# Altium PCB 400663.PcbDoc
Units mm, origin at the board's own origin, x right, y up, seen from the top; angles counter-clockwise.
Board outline 63.5 x 80 mm, 6 copper layers (Top Layer, Mid-Layer 1, Mid-Layer 2, Mid-Layer 3, Mid-Layer 4, Bottom Layer), stack 1.671 mm thick; 78 components, 32 nets, 270 pads, 197 vias.
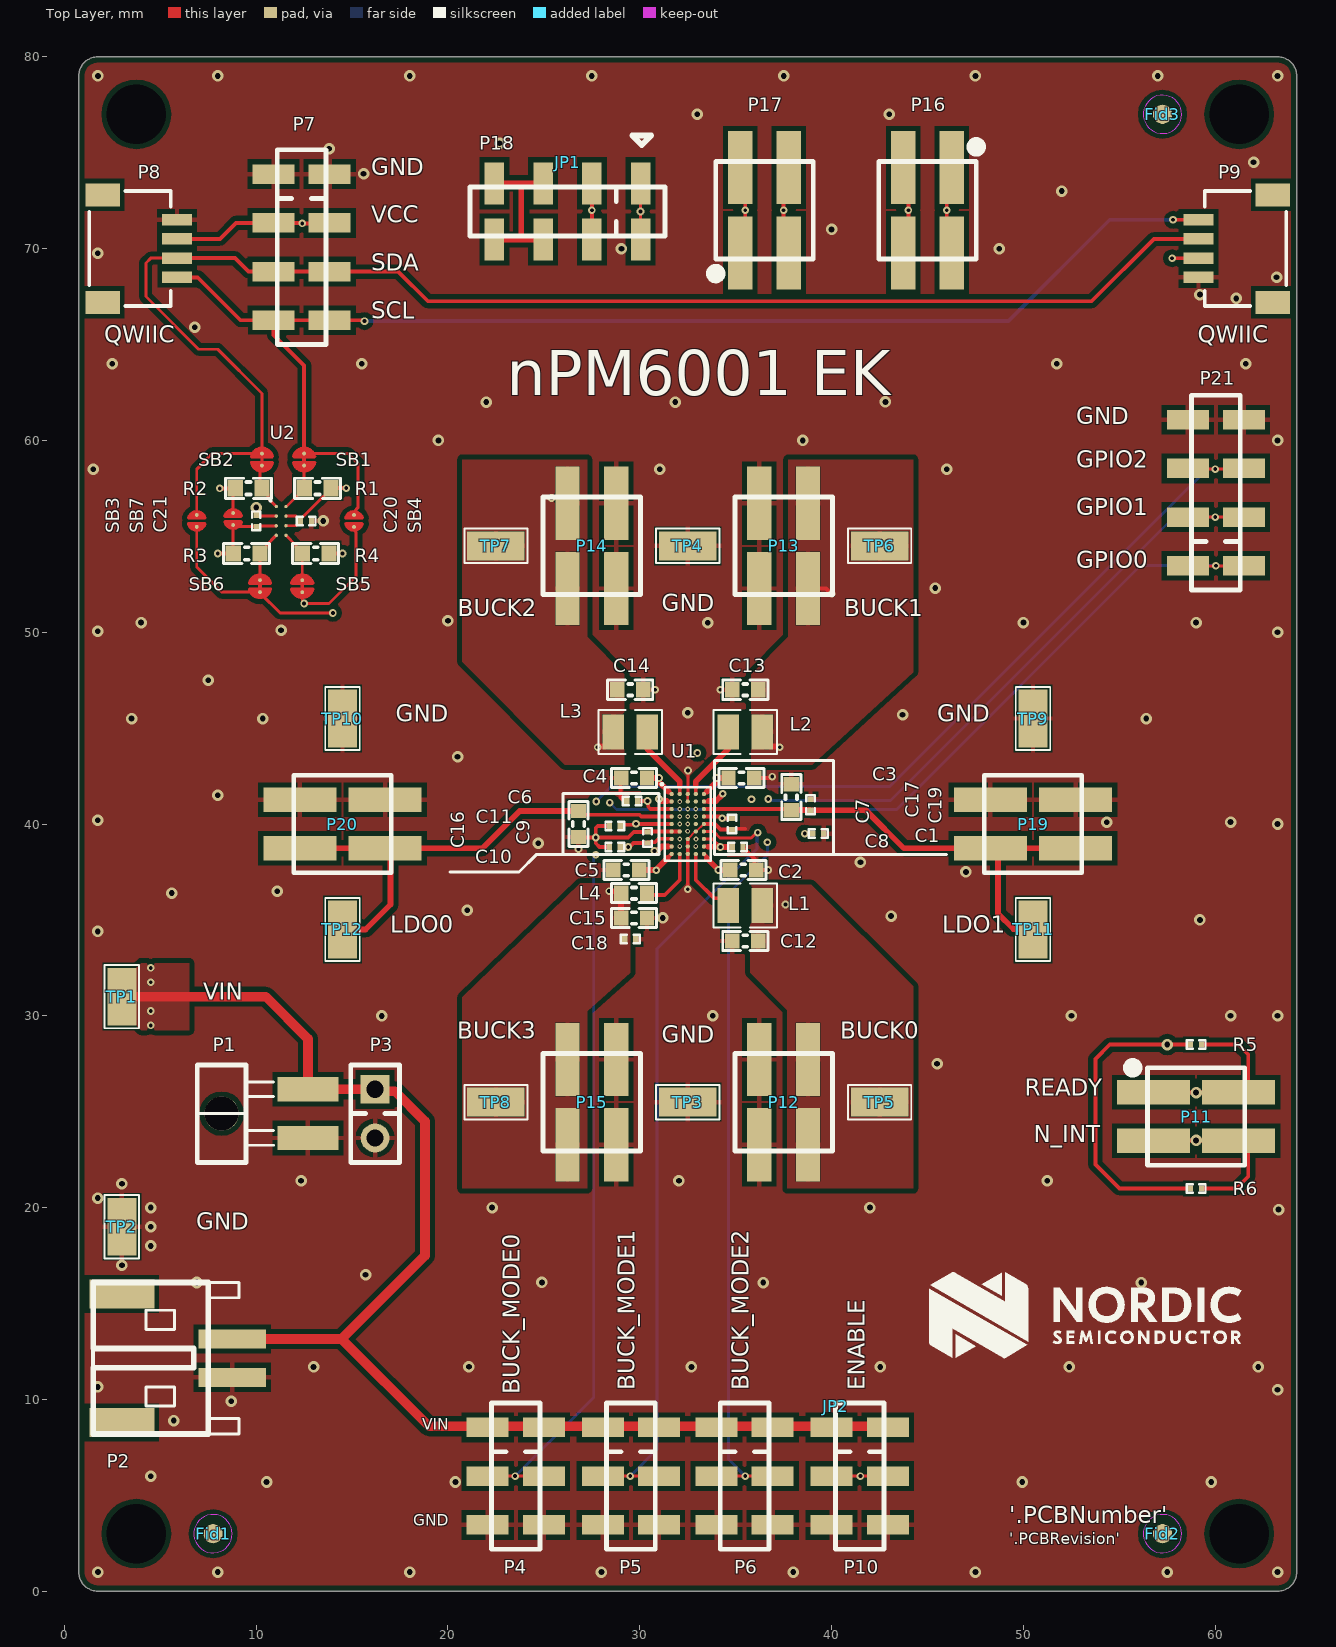
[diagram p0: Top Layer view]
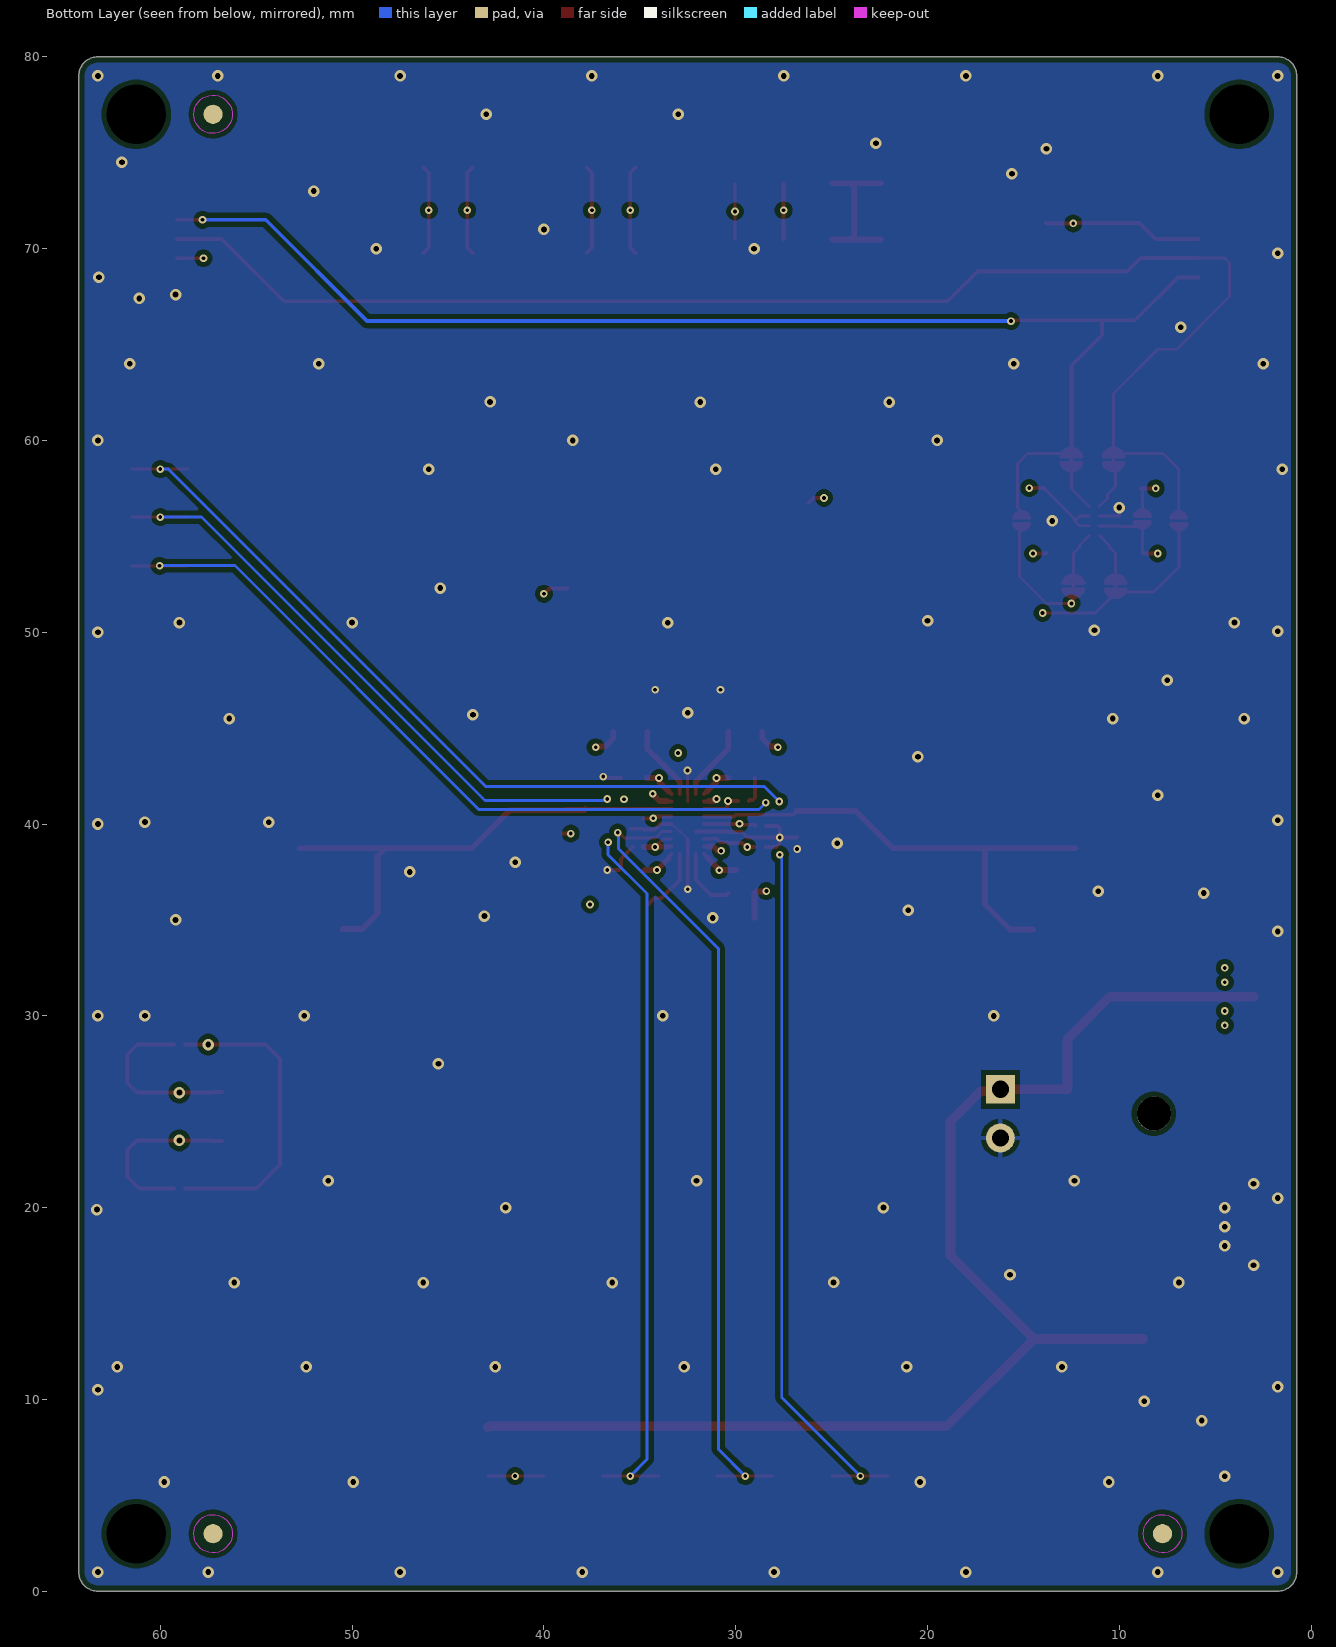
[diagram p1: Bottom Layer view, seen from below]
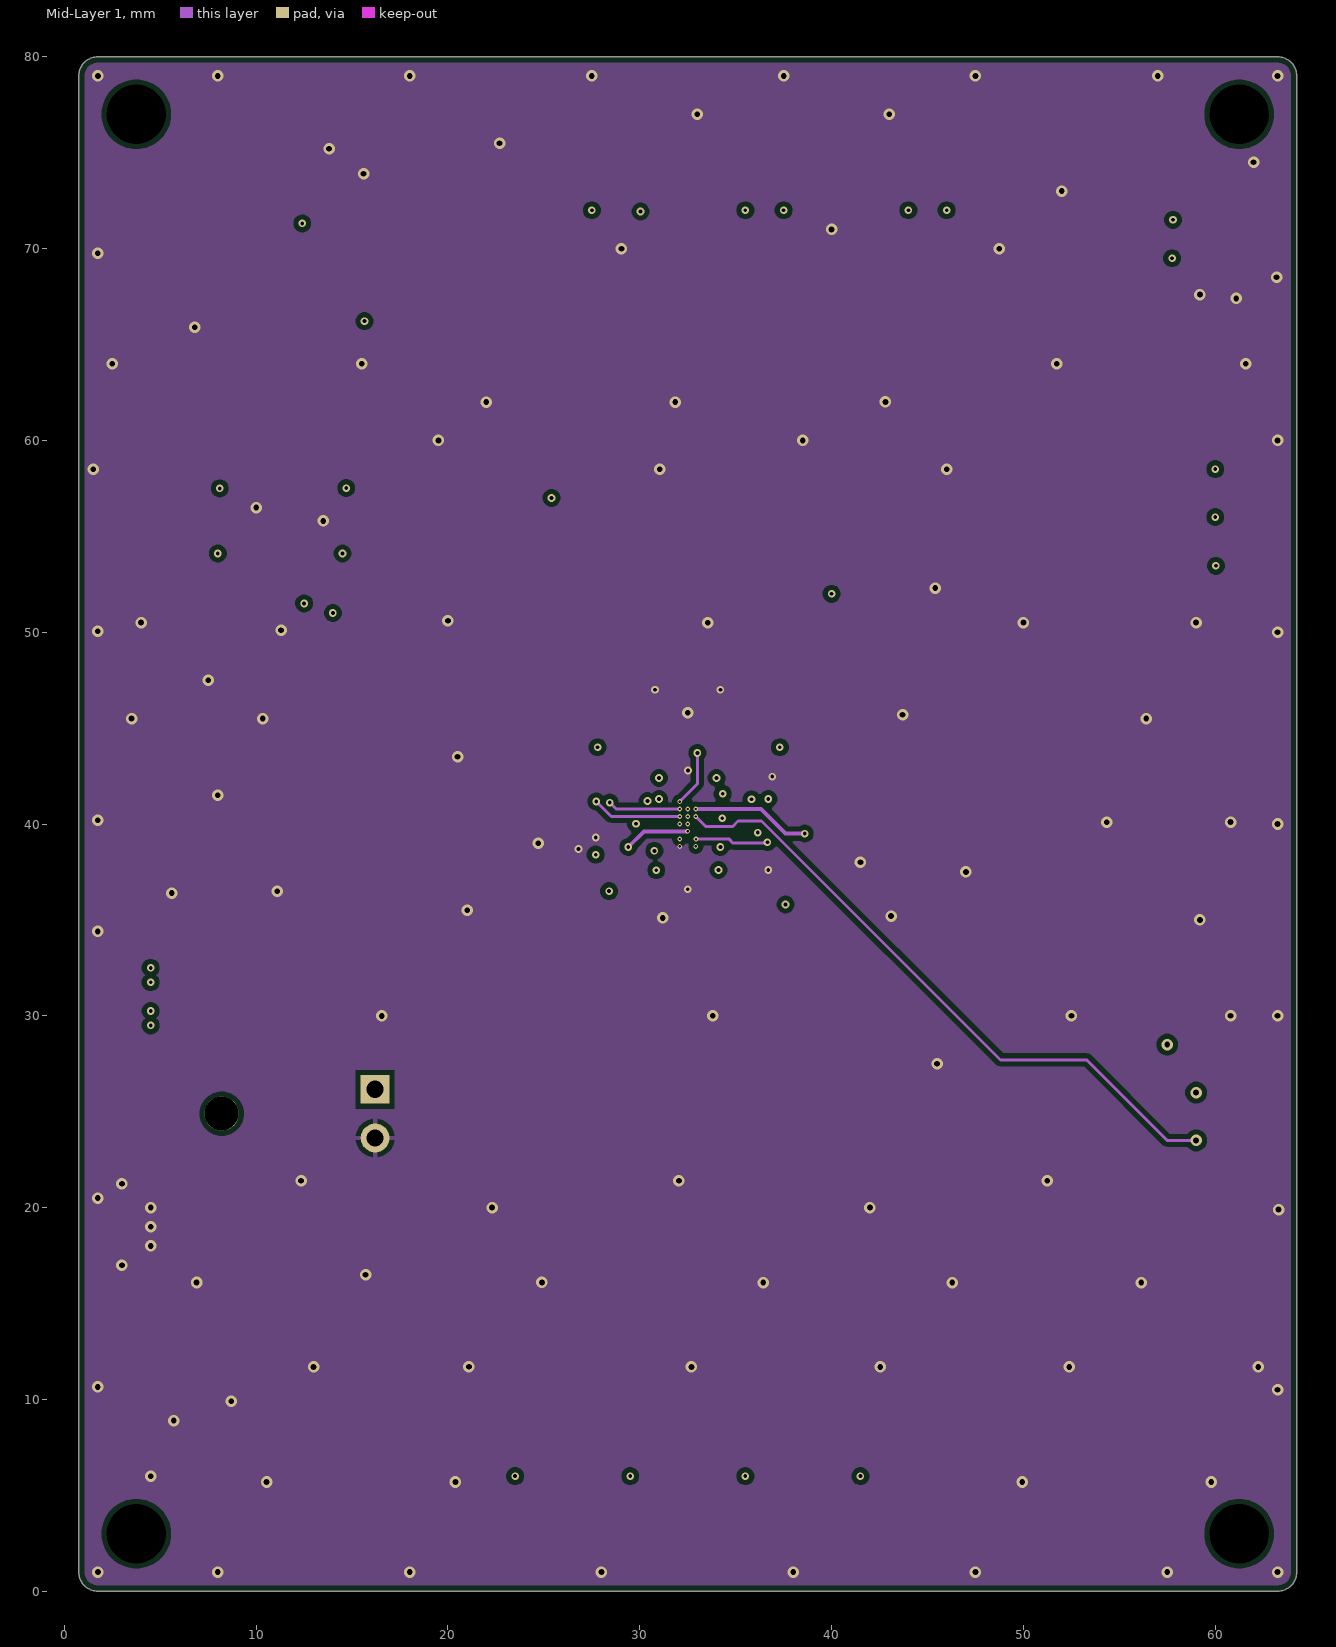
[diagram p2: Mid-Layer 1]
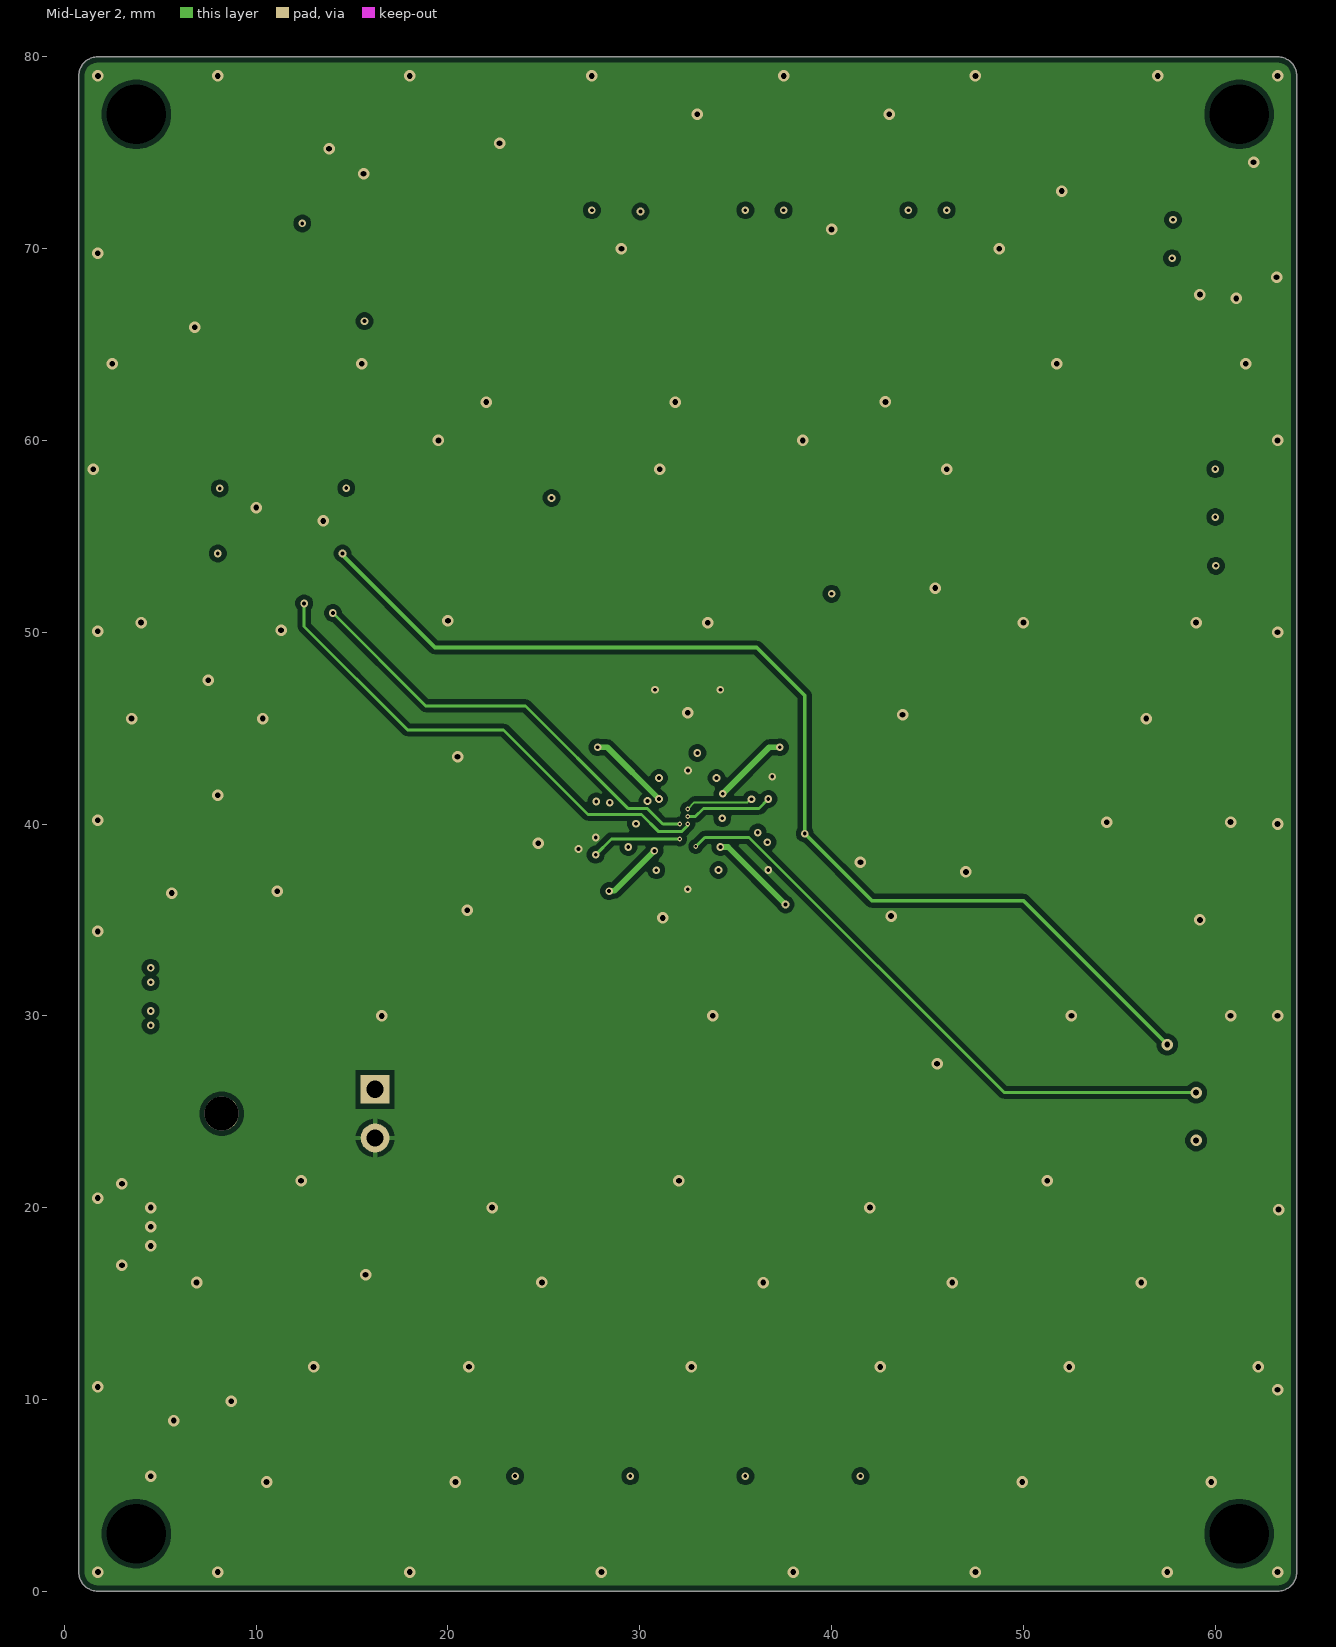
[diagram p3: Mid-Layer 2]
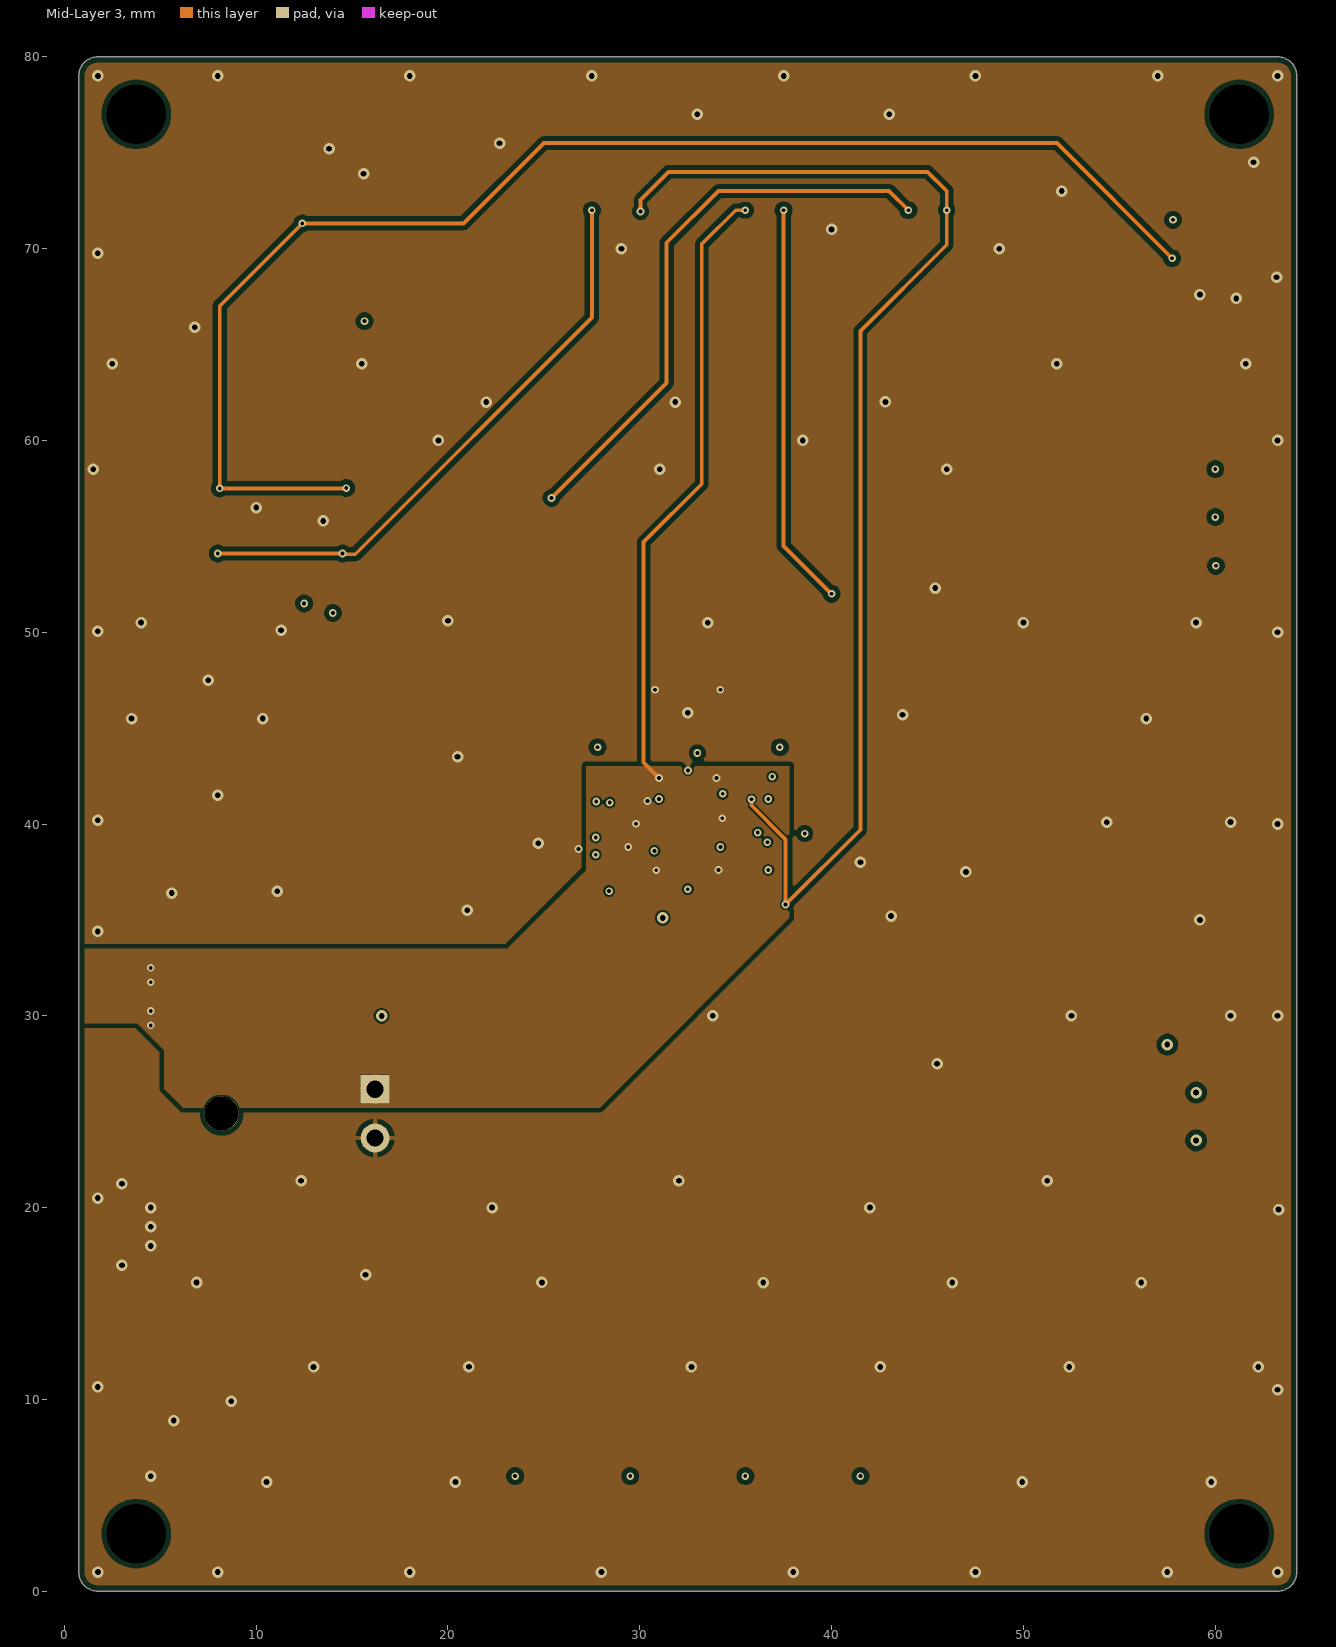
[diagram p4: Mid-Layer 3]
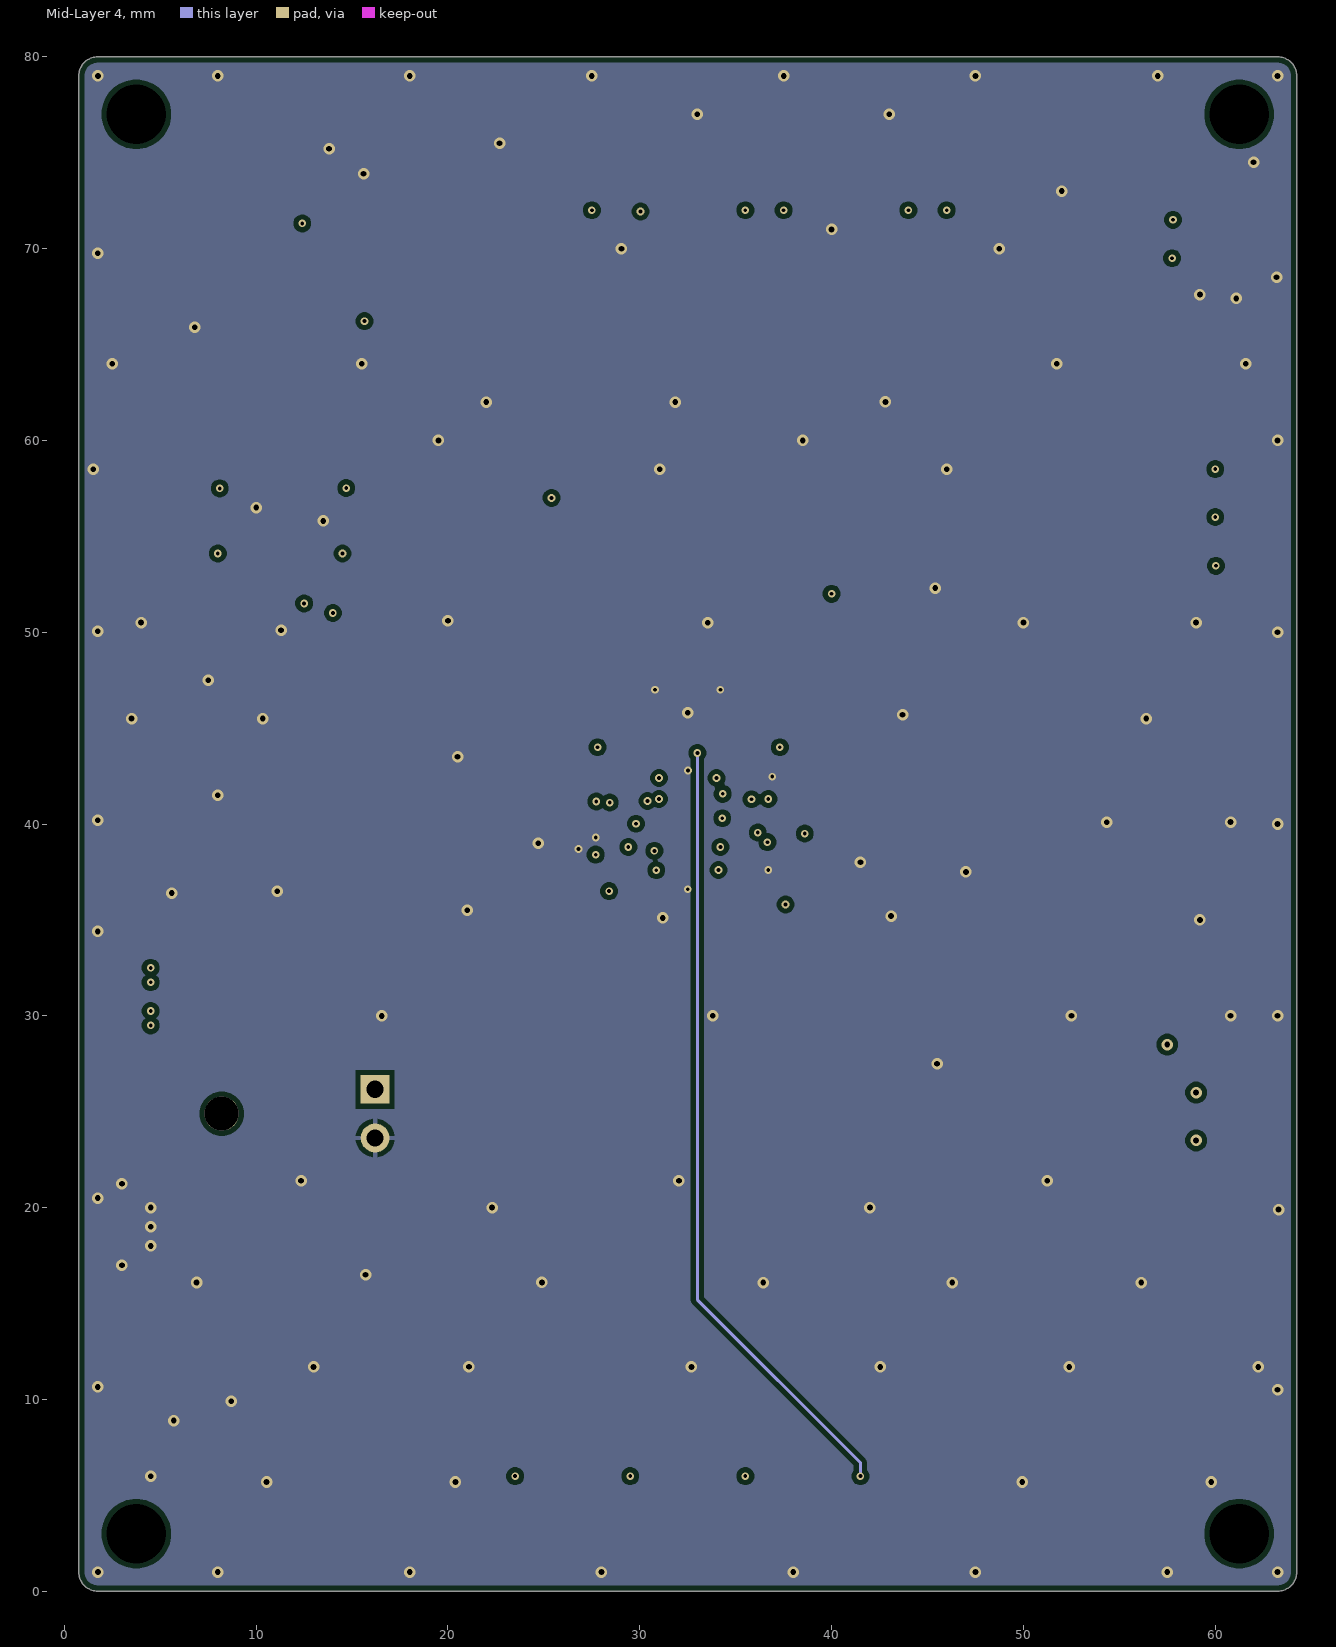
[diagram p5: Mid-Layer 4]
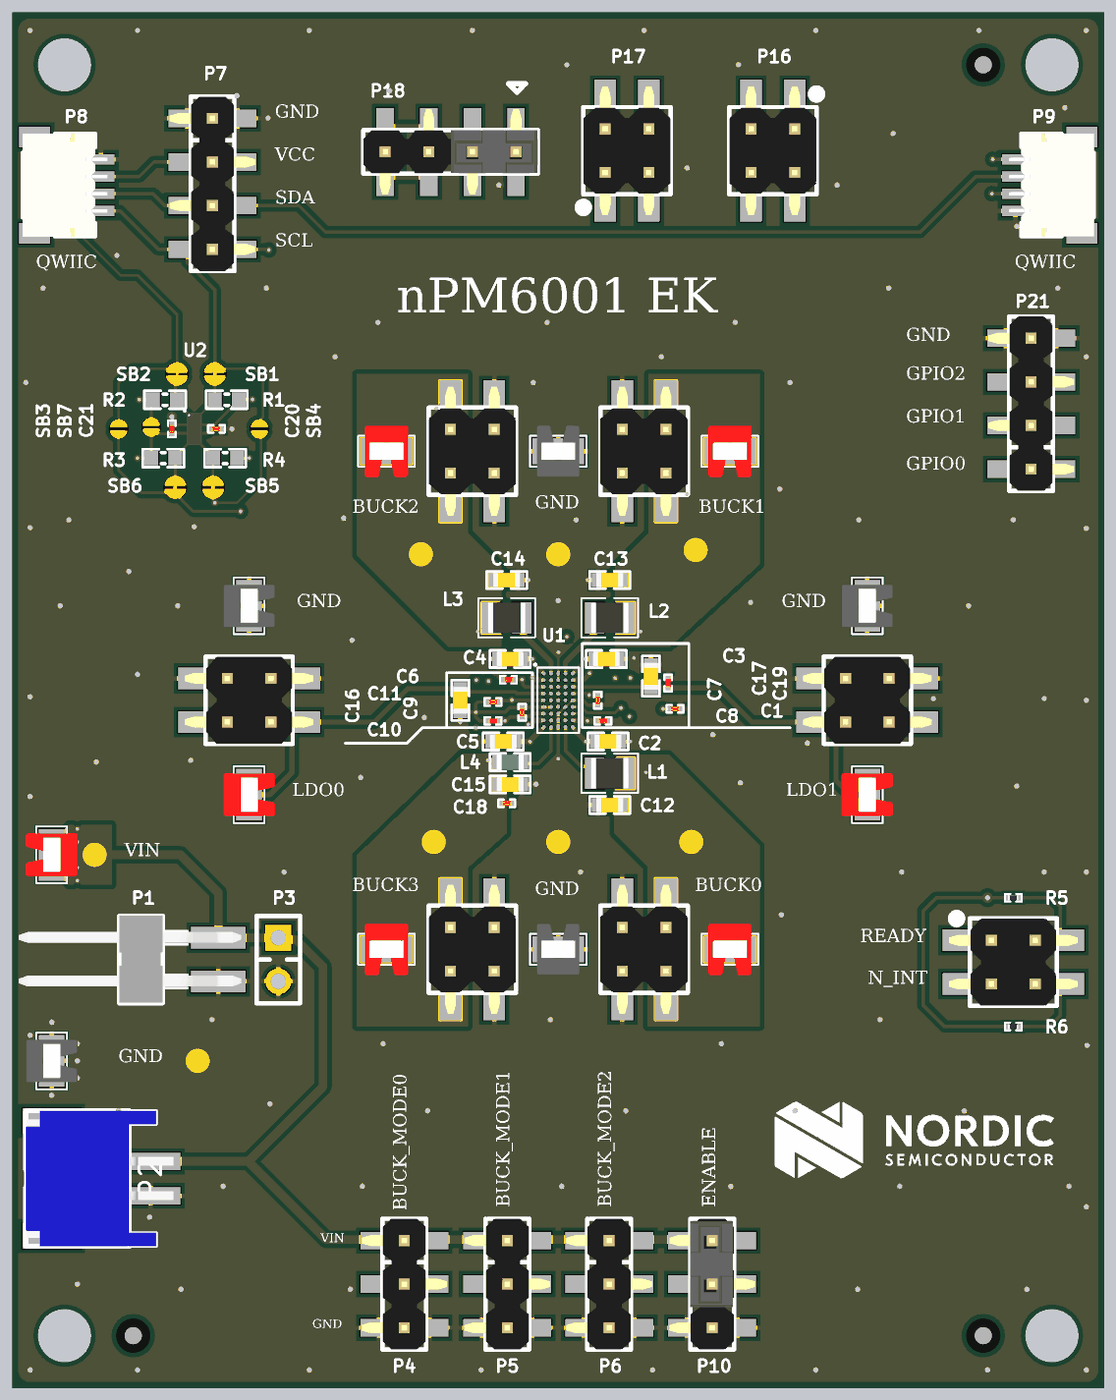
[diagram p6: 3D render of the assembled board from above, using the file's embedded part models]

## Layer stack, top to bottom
Top Solder: solder mask 0.0102, Solder Resist, Dk 3.5
Top Layer: signal copper 0.018
Dielectric1: prepreg 0.065, FR-4, Dk 4.2
Mid-Layer 1: signal copper 0.035
Dielectric2: core 0.51, FR-4, Dk 4.2
Mid-Layer 2: signal copper 0.035
Dielectric3: prepreg 0.345, FR-4, Dk 4.2
Mid-Layer 3: signal copper 0.035
Dielectric 5: core 0.51, FR-4, Dk 4.2
Mid-Layer 4: signal copper 0.035
Dielectric 4: prepreg 0.065, FR-4, Dk 4.2
Bottom Layer: signal copper 0.018
Bottom Solder: solder mask 0.0102, Solder Resist, Dk 3.5

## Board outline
0.75,1 ccw(c1.75,1) 1.75,0 63.25,0 ccw(c63.25,1) 64.25,1 64.25,79 ccw(c63.25,79) 63.25,80 1.75,80 ccw(c1.75,79) 0.75,79

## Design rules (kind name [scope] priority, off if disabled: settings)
BoardOutlineClearance [All] p1: gap=0.3 ignorepadtopadclearanceinfootprint=FALSE
Clearance Clearance_MicroVia [AsMM(ViaDiameter) = 0.30 vs AsMM(ViaDiameter) = 0.3] p1: gap=0.1 ignorepadtopadclearanceinfootprint=FALSE except(0: Arc-Hole Track-Hole SMDPad-Hole THPad-Hole Via-Hole Fill-Hole Poly-Hole Region-Hole Text-Hole)
Clearance Polygon_Clearance [(InNamedPolygon('Top_Layer-GND')) or (InNamedPolygon('Bottom_Layer-GND')) or (InNamedPolygon('Mid_Layer_1-GND')) or (InNamedPolygon('Mid_Layer_2-GND')) or (InNamedPolygon('Mid_Layer_3-GND')) or (InNamedPolygon('Mid_Layer_4-GND'))] p2: gap=0.254 ignorepadtopadclearanceinfootprint=FALSE except(0: Arc-Hole Track-Hole SMDPad-Hole THPad-Hole Via-Hole Fill-Hole Poly-Hole Region-Hole Text-Hole)
Clearance [All] p3: gap=0.1 ignorepadtopadclearanceinfootprint=FALSE
ComponentClearance [All] p1: gap=0.05 collisioncheckmode=3 verticalgap=0 showdistances=FALSE
DiffPairsRouting [All] p1: maxlimit=0.254 minlimit=0.15 mostfreqgap=0.254 toplayer_maxgap=0.15 toplayer_prefgap=0.15 toplayer_minwidth=0.381 toplayer_maxwidth=0.381 toplayer_prefwidth=0.381 midlayer1_mingap=0.254 midlayer1_minwidth=0.381 midlayer1_maxwidth=0.381 midlayer1_prefwidth=0.381 midlayer2_mingap=0.254 midlayer2_minwidth=0.381 midlayer2_maxwidth=0.381 midlayer2_prefwidth=0.381 midlayer3_mingap=0.254 midlayer3_minwidth=0.381 midlayer3_maxwidth=0.381 midlayer3_prefwidth=0.381 midlayer4_mingap=0.254 midlayer4_minwidth=0.381 midlayer4_maxwidth=0.381 midlayer4_prefwidth=0.381 bottomlayer_maxgap=0.15 bottomlayer_prefgap=0.15 bottomlayer_minwidth=0.381 bottomlayer_maxwidth=0.381 bottomlayer_prefwidth=0.381 maxuncoupledlength=12.7
FabricationTestPointUsage TestPointUsage [All] p1: valid=0 allowmultiple=FALSE
FabricationTestpoint Testpoint [All] p1: side=3 testpointundercomponent=TRUE minsize=1.016 maxsize=2.54 preferedsize=1.524 minholesize=0 maxholesize=1.016 preferedholesize=0.813 testpointgrid=0.025 allowsidetop=TRUE allowsidebottom=TRUE usegrid=TRUE gridtolerance=0
HoleSize [All] p1: absolutevalues=TRUE maxlimit=5 minlimit=0.1 maxpercent=80.000 minpercent=20.000
MinimumAnnularRing [All] p1 off: minimumring=0.152
PolygonConnect "Power lines connection" [InNetClass('POWER') vs InNetClass('POWER')] p1: connectstyle=Direct reliefconductorwidth=0.254 reliefentries=4 polygonreliefangle="90 Angle" airgapwidth=0.254
PolygonConnect PolygonConnect_1 [isVia and innet(gnd)] p2: connectstyle=Direct reliefconductorwidth=0.254 reliefentries=4 polygonreliefangle="90 Angle" airgapwidth=0.254
PolygonConnect [Not InNetClass('POWER') vs Not InNetClass('POWER')] p3: connectstyle=Relief reliefconductorwidth=0.254 reliefentries=4 polygonreliefangle="90 Angle" airgapwidth=0.254
RoutingVias [All] p1: holewidth=0.711 width=1.27 viastyle="Through Hole" minholewidth=0.711 minwidth=1.27 maxholewidth=0.711 maxwidth=1.27 useviatemplates=TRUE viatemplateguid#1={E10108A7-C3D0-4C8E-BCC4-782C824E42E2} viatemplateguid#2={3A7E0D42-F5CB-4729-A8CA-0CF221B85944} viatemplatename#1=v25h12m0 viatemplatename#2=v40h20m0mx0
SilkToSolderMaskClearance SilkscreenOverComponentPads [IsPad] p1: minsilkscreentomaskgap=0.254 clearancetoexposedcopper=TRUE
SolderMaskExpansion [All] p1: expansion=0.076 istentingtop=FALSE
SupplyNets "Schematic Supply Nets" [InNet('VIN')] p1: voltage=0.000
Width [All] p1: maxlimit=1 minlimit=0.1 preferedwidth=0.15 minimp=50.000000 maximp=50.000000 favimp=50.000000
24 further rules are at their usual default settings.

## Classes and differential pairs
net class POWER: PMIC_VCC VIN VOUT_BUCK0 VOUT_BUCK1 VOUT_BUCK2 VOUT_BUCK3 VOUT_VLDO0 VOUT_VLDO1
component class "Level Shifter": C20 C21 R1 R2 R3 R4 SB1 SB2 SB3 SB4 SB5 SB6 SB7 U2
component class nPM6001: C1 C2 C3 C4 C5 C6 C7 C8 C9 C10 C11 C12 C13 C14 C15 C16 C17 C18 C19 L1 L2 L3 L4 R5 R6 U1
component class Connectors: JP1 JP2 P1 P2 P3 P4 P5 P6 P7 P8 P9 P10 P11 P12 P13 P14 P15 P16 P17 P18 P19 P20 P21 TP1 TP2 TP3 TP4 TP5 TP6 TP7 TP8 TP9 TP10 TP11 TP12

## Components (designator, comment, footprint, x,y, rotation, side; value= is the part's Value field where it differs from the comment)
C1 "1.0µF" CAPC0603X03L_C 39.3,39.5 r0 top
C2 "10µF" CAPC1608X06L 35.4,37.6 r180 top
C3 "10µF" CAPC1608X06L 35.3,42.4 r180 top
C4 "10µF" CAPC1608X06L 29.7,42.4 r0 top
C5 "10µF" CAPC1608X06L 29.3,37.6 r0 top
C6 "1.0µF" CAPC0603X03L_C 29.6,41.2 r180 top
C7 "1.0µF" CAPC0603X03L_C 34.8,40 r270 top
C8 "1.0µF" CAPC0603X03L_C 35.1,38.8 r0 top
C9 "1.0µF" CAPC0603X03L_C 30.4,39.3 r90 top
C10 "1.0µF" CAPC0603X03L_C 28.7,38.8 r180 top
C11 "1.0µF" CAPC0603X03L_C 28.7,39.9 r180 top
C12 "10µF" CAPC1608X06L 35.5,33.897 r0 top
C13 "10µF" CAPC1608X06L 35.5,47 r0 top
C14 "10µF" CAPC1608X06L 29.5,47 r180 top
C15 "4.7µF" CAPC1608X06L 29.7,35.1 r180 top
C16 "10µF" CAPC1608X06L 26.8,40 r90 top
C17 "10µF" CAPC1608X06L 37.9,41.4 r270 top
C18 "1.0µF" CAPC0603X03L_C 29.5,34 r0 top
C19 "1.0µF" CAPC0603X03L_C 38.9,41 r90 top
C20 "100nF" CAPC0603X03L_C 12.6,55.8 r180 top
C21 "100nF" CAPC0603X03L_C 10,55.8 r270 top
Fid1 "Fiducial mark" Fiducial 7.75,3 r0 top value=N.A.
Fid2 "Fiducial mark" Fiducial 57.25,3 r0 top value=N.A.
Fid3 "Fiducial mark" Fiducial 57.25,77 r0 top value=N.A.
JP1 "Shunt 2.54mm" Shunt_2.54mm_Horizontal 26.25,74.5 r0 top
JP2 "Shunt 2.54mm" Shunt_2.54mm_Horizontal 40.209,9.649 r270 top
L1 "2.2µH" INDC2016X10N 35.5,35.749 r0 top
L2 "2.2µH" INDC2016X10N 35.5,44.8 r0 top
L3 "2.2µH" INDC2016X10N 29.5,44.8 r180 top
L4 "470nH" INDC1608X06L 29.7,36.397 r180 top
P1 "Pin List 1x2, Angled" LIST_ANG_1x2-SMD-2.54MM 12.696,24.9 r270 top
P2 "HDR-2, 2mm" S2B-PH-SM4-TB 8.75,12.15 r270 top
P3 "Pin List 1x2" LIST_1x2-NC 16.2,24.9 r270 top
P4 "BUCK_MODE0" LIST_1x3_SMD 23.535,8.54 r270 top value="Pin List 1x3"
P5 "BUCK_MODE1" LIST_1x3_SMD 29.535,8.54 r270 top value="Pin List 1x3"
P6 "BUCK_MODE2" LIST_1x3_SMD 35.465,8.54 r270 top value="Pin List 1x3"
P7 "Pin List 1x4" LIST_1x4_SMD 12.365,73.88 r270 top
P8 "QWIIC" SM04B-SRSS-TB 2,70 r270 top value=SM04B-SRSS-TB
P9 "QWIIC" SM04B-SRSS-TB 63,70 r90 top value=SM04B-SRSS-TB
P10 "ENABLE" LIST_1x3_SMD 41.465,8.54 r270 top value="Pin List 1x3"
P11 "Conn 2x2" HDR_2x2-SMD 59,24.75 r270 top
P12 "Conn 2x2" HDR_2x2-SMD 37.5,25.5 r180 top
P13 "Conn 2x2" HDR_2x2-SMD 37.5,54.5 r180 top
P14 "Conn 2x2" HDR_2x2-SMD 27.5,54.5 r0 top
P15 "Conn 2x2" HDR_2x2-SMD 27.5,25.5 r0 top
P16 "Conn 2x2" HDR_2x2-SMD 45,72 r180 top
P17 "Conn 2x2" HDR_2x2-SMD 36.5,72 r0 top
P18 "Pin List 1x4" LIST_1x4_SMD 30.04,71.935 r180 top
P19 "Conn 2x2" HDR_2x2-SMD 50.5,40 r90 top
P20 "Conn 2x2" HDR_2x2-SMD 14.5,40 r90 top
P21 "Pin List 1x4" LIST_1x4_SMD 60.035,53.46 r90 top
R1 "N.C." RESC1608X06L_NC 13.2,57.5 r0 top
R2 "N.C." RESC1608X06L_NC 9.6,57.5 r180 top
R3 "N.C." RESC1608X06L_NC 9.5,54.1 r180 top
R4 "N.C." RESC1608X06L_NC 13.1,54.1 r0 top
R5 "10k" RESC0603X03L_C 59,28.5 r180 top
R6 "10k" RESC0603X03L_C 59,21 r180 top
SB1 "Solderbridge" Solderbridge_SHORTED_0.4 12.5,59 r90 top net-tie
SB2 "Solderbridge" Solderbridge_SHORTED_0.4 10.3,59 r90 top net-tie
SB3 "Solderbridge" Solderbridge 6.9,55.8 r90 top
SB4 "Solderbridge" Solderbridge 15.1,55.8 r90 top
SB5 "Solderbridge" Solderbridge_SHORTED_0.4 12.4,52.4 r90 top net-tie
SB6 "Solderbridge" Solderbridge_SHORTED_0.4 10.2,52.4 r90 top net-tie
SB7 "Solderbridge" Solderbridge 8.8,55.9 r90 top
TP1 "VIN" Keystone_5190TR 3,31 r270 top value=TP
TP2 "GND" Keystone_5191TR 3,19 r90 top value=TP
TP3 "GND" Keystone_5191TR 32.5,25.5 r180 top value=TP
TP4 "GND" Keystone_5191TR 32.5,54.5 r180 top value=TP
TP5 "BUCK0" Keystone_5190TR 42.5,25.5 r0 top value=TP
TP6 "BUCK1" Keystone_5190TR 42.5,54.5 r0 top value=TP
TP7 "BUCK2" Keystone_5190TR 22.5,54.5 r0 top value=TP
TP8 "BUCK3" Keystone_5190TR 22.5,25.5 r0 top value=TP
TP9 "GND" Keystone_5191TR 50.5,45.5 r90 top value=TP
TP10 "GND" Keystone_5191TR 14.5,45.5 r90 top value=TP
TP11 "LDO1" Keystone_5190TR 50.5,34.5 r90 top value=TP
TP12 "LDO0" Keystone_5190TR 14.5,34.5 r90 top value=TP
U1 "nPM6001-CAAA" BGA45C40P5X9_217X364X49 32.5,40 r0 top
U2 "TXS0102YZTR" BGA8C50P2X4_89X189X50 11.3,55.8 r0 top

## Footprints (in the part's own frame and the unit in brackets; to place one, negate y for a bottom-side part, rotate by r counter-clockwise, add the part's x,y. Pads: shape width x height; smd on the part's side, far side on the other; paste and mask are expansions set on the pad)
BGA8C50P2X4_89X189X50 [mm] "BGA, 8-Leads, Body 0,89x1,89mmx0,50mm, Pitch 0,50mm"
  round 0.17 smd: A1(-0.25,0.75) A2(0.25,0.75) B1(-0.25,0.25) B2(0.25,0.25) C1(-0.25,-0.25) C2(0.25,-0.25) D1(-0.25,-0.75) D2(0.25,-0.75)
  silkscreen extent -0.6,1 -0.5,1.1, body extent -0.45,-0.94 0.45,0.94, height 0.5
BGA45C40P5X9_217X364X49 [mm] "BGA, 45-Leads, Body 2.17x3.64mmx0.49mm, Pitch 0.40mm"
  round 0.22 smd mask+0.05: A1(-0.84,1.56) A2(-0.42,1.56) A3(0,1.56) A4(0.42,1.56) A5(0.84,1.56) B1(-0.84,1.17) B2(-0.42,1.17) B3(0,1.17) B4(0.42,1.17) B5(0.84,1.17) C1(-0.84,0.78) C2(-0.42,0.78) C3(0,0.78) C4(0.42,0.78) C5(0.84,0.78) D1(-0.84,0.39) D2(-0.42,0.39) D3(0,0.39) D4(0.42,0.39) D5(0.84,0.39) E1(-0.84,0) E2(-0.42,0) E3(0,0) E4(0.42,0) E5(0.84,0) F1(-0.84,-0.39) F2(-0.42,-0.39) F3(0,-0.39) F4(0.42,-0.39) F5(0.84,-0.39) G1(-0.84,-0.78) G2(-0.42,-0.78) G3(0,-0.78) G4(0.42,-0.78) G5(0.84,-0.78) H1(-0.84,-1.17) H2(-0.42,-1.17) H3(0,-1.17) H4(0.42,-1.17) H5(0.84,-1.17) J1(-0.84,-1.56) J2(-0.42,-1.56) J3(0,-1.56) J4(0.42,-1.56) J5(0.84,-1.56)
  silkscreen extent -1.39,-1.91 1.21,2.12, body extent -1.14,-1.85 1.14,1.84, height 0.41
CAPC0603X03L_C [mm] "Chip Capacitor, 2-Leads, Body 0.6x0.3mm, IPC High Density"
  rect 0.27x0.3 smd mask+0.05: 1(-0.285,0) 2(0.285,0)
  silkscreen extent -0.49,-0.22 0.49,0.22, body extent -0.3,-0.15 0.31,0.15, height 0.3
CAPC1608X06L [mm] "Chip Capacitor, 2-Leads, Body 1.6x0.8mm, IPC High Density"
  rect 0.75x0.8 smd: 1(-0.675,0) 2(0.675,0)
  silkscreen extent -1.17,-0.5 1.17,0.5, body extent -0.8,-0.43 0.8,0.43, height 0.8
Fiducial [mm] "Fiducial Mark"
  round 1 smd paste+0 mask+0.5: 0(0,0)
  round 1 smd far side paste+0 mask+0.5: 0(0,0)
  Top Layer keep-out circle w0.01: c0,0 r1
  Bottom Layer keep-out circle w0.01: c0,0 r1
HDR_2x2-SMD [mil] "Board-Board Conn, Header, 4-way, 2-row"
  rect 50x150 smd: 1(-50,-87.5) 2(-50,87.5) 3(50,-87.5) 4(50,87.5)
  silkscreen extent -110,-140 100,100, body extent -100,-148 100,148, height 382
INDC1608X06L [mm] "Chip Inductor, 2-Leads, Body 1.6x0.8mm, IPC High Density"
  rect 0.75x0.8 smd: 1(-0.675,0) 2(0.675,0)
  silkscreen extent -1.17,-0.5 1.17,0.5, body extent -0.8,-0.48 0.8,0.48, height 0.8
INDC2016X10N [mm] "Chip Inductor, 2-Leads, Body 2.00x1.60mm, IPC Medium Density"
  rect 1.13x1.82 smd: 1(-0.885,0) 2(0.885,0)
  silkscreen extent -1.65,-1.14 1.65,1.14, body extent -1.1,-0.9 1.1,0.9, height 1
Keystone_5190TR [mm]
  rect 3x1.5 smd: 1(0,0)
  silkscreen extent -1.65,-0.9 1.65,0.9, body extent -1.25,-1.5 1.25,1.5, height 2.4
Keystone_5191TR [mm]
  rect 3x1.5 smd: 1(0,0)
  silkscreen extent -1.65,-0.9 1.65,0.9, body extent -1.25,-1.5 1.25,1.5, height 2.4
LIST_1x2-NC [mm] "Pin List, 2.54mm through hole"
  rect 1.5x1.5 hole 0.9: 1(-1.27,0)
  round 1.5 hole 0.9: 2(1.27,0)
  silkscreen extent -2.54,-1.27 2.54,1.27
LIST_1x3_SMD [mm] "Pin List, 2.54mm, SMD"
  rect 1.02x2.19 smd: 1(0,1.465) 1(0,-1.465) 2(2.54,1.465) 2(2.54,-1.465) 3(5.08,-1.465) 3(5.08,1.465)
  silkscreen extent -1.27,-1.27 6.35,1.27, body extent -1.27,-2.5 6.35,2.5, height 9.82
LIST_1x4_SMD [mm] "Pin List, 2.54mm, SMD"
  rect 1.02x2.19 smd: 1(0,1.465) 1(0,-1.465) 2(2.54,1.465) 2(2.54,-1.465) 3(5.08,-1.465) 3(5.08,1.465) 4(7.62,-1.465) 4(7.62,1.465)
  silkscreen extent -1.27,-1.27 8.89,1.27, body extent -1.27,-2.5 8.89,2.5, height 9.82
LIST_ANG_1x2-SMD-2.54MM [mm] "Pin List, 2.54mm, Surface Mount, Angled"
  round 1.78 hole 1.78 unplated: 0(0,-4.496)
  rect 1.27x3.18 smd: 1(-1.27,0) 2(1.27,0)
  silkscreen extent -2.54,-5.77 2.54,-1.8, body extent -2.56,-11.61 2.52,1.35, height 3.03
RESC0603X03L_C [mm] "Chip Resistor, 2-Leads, Body 0.6x0.3mm, IPC High Density"
  rect 0.27x0.3 smd: 1(-0.285,0) 2(0.285,0)
  silkscreen extent -0.49,-0.22 0.49,0.22, body extent -0.3,-0.15 0.3,0.15, height 0.23
RESC1608X06L_NC [mm] "Chip Resistor, 2-Leads, Body 1.6x0.8mm, IPC High Density"
  rect 0.8x0.85 smd: 1(-0.7,0) 2(0.7,0)
  silkscreen extent -1.2,-0.53 1.2,0.53
S2B-PH-SM4-TB [mm] "JST, PH connector, side entry SMD, 2mm pitch"
  rect 1.5x3.4 smd: 0(-3.35,-5.75) 0(3.35,-5.75)
  rect 1x3.5 smd: 1(-1,0) 2(1,0)
  silkscreen extent -3.95,-7.25 3.95,0.35, body extent -3.95,-7.25 3.95,1.35, height 5.5
Shunt_2.54mm_Horizontal [mm]
  body extent 0,-3.78 5.03,-1.3, height 9
SM04B-SRSS-TB [mm]
  rect 1.2x1.8 smd: 0(-2.8,0) 0(2.8,0)
  rect 0.6x1.55 smd: 1(-1.5,3.875) 2(-0.5,3.875) 3(0.5,3.875) 4(1.5,3.875)
  silkscreen extent -3,-0.7 3,3.55, body extent -3,-0.7 3,4.25, height 2.96
Solderbridge [mm]
  round 0.2 smd paste-10: 1(-0.312,0) 2(0.312,0)
  Top Layer region: -0.077,-0.432 -0.152,-0.505 -0.271,-0.467 -0.335,-0.424 -0.409,-0.351 -0.462,-0.292 -0.521,-0.193 -0.549,-0.099 -0.544,0.122 -0.518,0.193 -0.434,0.33 -0.351,0.411 -0.259,0.469 -0.157,0.5 -0.107,0.483 -0.077,0.43
  Top Layer region: 0.077,0.432 0.152,0.505 0.271,0.467 0.335,0.424 0.409,0.351 0.462,0.292 0.521,0.193 0.549,0.099 0.544,-0.122 0.518,-0.193 0.434,-0.33 0.351,-0.411 0.259,-0.469 0.157,-0.5 0.107,-0.483 0.077,-0.43
  Top Layer lines w0.152: -0.153,0.431 ccw(c-0.042,0) -0.461,0.149 ccw(c-0.042,0) -0.487,0 ccw(c-0.042,0) -0.153,-0.431 ; 0.153,0.431 cw(c0.042,0) 0.461,0.149 cw(c0.042,0) 0.487,0 cw(c0.042,0) 0.153,-0.431
Solderbridge_SHORTED_0.4 [mm]
  round 0.2 smd paste-10: 1(-0.312,0) 2(0.312,0)
  Top Layer region: 0.077,0.553 0.203,0.512 0.335,0.424 0.409,0.351 0.462,0.292 0.521,0.193 0.549,0.099 0.544,-0.122 0.518,-0.193 0.434,-0.33 0.351,-0.411 0.152,-0.536 0.077,-0.559
  Top Layer region: -0.077,-0.553 -0.129,-0.605 -0.205,-0.554 -0.409,-0.351 -0.462,-0.292 -0.521,-0.193 -0.549,-0.099 -0.544,0.122 -0.518,0.193 -0.434,0.33 -0.351,0.411 -0.259,0.469 -0.159,0.556 -0.08,0.565
  Top Layer lines w0.152: -0.156,0.557 ccw(c-0.035,0) -0.153,-0.558 ; 0.153,0.557 cw(c0.03,0) 0.153,-0.557
  Top Layer lines w0.2: -0.312,0 0.363,0

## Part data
C1 C6 C7 C8 C9 C10 C11: library part C0201-1µ0, "Capacitor, X5R, ±10%", Manufacturer=N.A., Part number IPS=00000001723, Supplier Part Number 1=1276-6795-1-ND
C2 C3 C4 C5 C12 C13 C14 C16 C17: library part C0603-10µ-10V-X7T-GRM188D71A106MA73, "Capacitor, X7T, ±20%, 10V", Manufacturer=Murata, Manufacturer Part Number=GRM188D71A106MA73, Part number IPS=00000004696, Part number Norautron=N.A., Supplier Part Number 1=490-7200-1-ND
C15: library part C0603-4µ7, "Capacitor, X5R, ±10%, 6.3V", Manufacturer=N.A., Part number IPS=00000007783, Part number NEMS=100200274
C18 C19: library part C0201-1µ0, "Capacitor, X5R, ±10%", Manufacturer=N.A., Part number IPS=00000001723, Part number NEMS=100200084, Supplier Part Number 1=1276-6795-1-ND
C20 C21: library part C0201-100n-25V-X5R, "Capacitor, Ceramic, X5R, ±10%, 25V", Manufacturer=Murata, Manufacturer Part Number=GRM033R61E104KE14J, Part number IPS=N.A., Part number NEMS=100200459, Supplier Part Number 1=490-14571-1-ND
Fid1 Fid2 Fid3: library part Fid-Mark, "Fiducial Mark", Manufacturer=N.A., Part number NEMS=100500073
JP1 JP2: library part "SHUNT JUMPER 2.54mm BLACK GOLD Horizontal (Obsolete)", "Shunt Jumper 2.54mm Black", Manufacturer=3M, Manufacturer Part Number=969102-0000-DA, Part number IPS=00000001916, Part number NEMS=100500644, Part number Norautron=N.A., Supplier Part Number 1=3M9580-ND
L1 L2 L3: library part CIGT201610EH2R2MNE, "FIXED IND 2.2UH 2.5A 87MOHM SMD", Manufacturer="Samsung Electro-Mechanics", Part number IPS=N.A., Part number Norautron=26521789, Supplier Part Number 1=1276-6901-1-ND
L4: library part L0603-470n-1.9A-85mohm, "FIXED IND 470NH 1.9A 85 MOHM SMD", Manufacturer="Taiyo Yuden", Manufacturer Part Number=MCFK1608TR47M, Part number IPS=N.A., Supplier Part Number 1=587-5625-1-ND
P1: library part "Pin List Ang 1x2 SMD, 2.54mm", "Pin List 1x2, 2.54mm (100mil), Right Angled, SMD", Manufacturer=W-CON, Manufacturer Part Number=1125B-1102S0Z135R2, Part number IPS=00000009972, Part number NEMS=100500354, Part number Norautron=N.A.
P2: library part S2B-PH-SM4-TB, "2.0mm pitch connector side entry SMD", Manufacturer="JST Sales America Inc.", Manufacturer Part Number=S2B-PH-SM4-TB(LF)(SN), Part number IPS=N.A., Part number NEMS=100500381
P3: library part "Pin List 1x2, N.C.", "Pin List 1x2, 2.54mm (100mil)", Manufacturer=N.A., Part number NEMS=100500298
P4 P5 P6 P10: library part "Pin List 1x3 SMD", "Pin List 1x3, 2.54mm (100mil), SMD", Manufacturer=W-CON, Manufacturer Part Number=1125-1103S0M116CR02, Part number IPS=N.A., Part number NEMS=100500306, Part number Norautron=26470016
P7 P18 P21: library part "Pin List 1x4 SMD", "Pin List 1x4, 2.54mm (100mil), SMD", Manufacturer=N.A., Part number NEMS=100500311, Supplier Part Number 1=TSM-104-01-L-SV-P-TR
P8 P9: library part SM04B-SRSS-TB, "JST SR/SH 1.0mm 4-pin", Manufacturer="JST Sales America Inc.", Part number IPS=N.A., Part number NEMS=100500540
P11 P12 P13 P14 P15 P16 P17 P19 P20: library part HDR_2x2_SMD_GOLD, "CONN HEADER 4POS .100\" VERT 15AU", Manufacturer=Molex, Manufacturer Part Number=15-91-0040, Part number IPS=N.A., Part number NEMS=100500132, Supplier Part Number 1=0015910040-ND
R1 R2 R3 R4: library part R0603-N.C., "Not mounted", Manufacturer=N.A., Part number NEMS=100100373
R5 R6: library part R0201-10k, "Resistor, ±1%, 0.05W", Manufacturer=N.A., Part number IPS=00000001255, Part number NEMS=100100065, Part number Norautron=26107101
SB1 SB2 SB5 SB6: library part "Solderbridge Shorted 0.4mm", "Shorted Solderbridge", Manufacturer=N.A., Part number NEMS=100500561
SB3 SB4 SB7: Manufacturer=N.A., Part number NEMS=100500458
TP1 TP5 TP6 TP7 TP8 TP11 TP12: library part "TP - Keystone 5190T", "Miniature SMT Test Point -Red P/N 5190TR", Manufacturer=Keystone, Manufacturer Part Number=5190T, Part number IPS=N.A., Part number NEMS=100500747, Supplier Part Number 1=36-5190TR-ND
TP2 TP3 TP4 TP9 TP10: library part "TP - Keystone 5191T", "Miniature SMT Test Point -Red P/N 5191TR", Manufacturer=Keystone, Manufacturer Part Number=5191T, Part number IPS=N.A., Part number NEMS=100500748, Supplier Part Number 1=36-5191TR-ND
U1: "Low-power and high efficiency PMIC", Manufacturer="Nordic Semiconductor", Part number IPS=N.A., Part number NEMS=102000251
U2: "Voltage Level Translator Bidirectional 1 Circuit 2 Channel 24Mbps 8-DSBGA", Manufacturer="Texas Instruments", Part number IPS=N.A., Part number NEMS=101900683, Supplier Part Number 1=296-TXS0102YZTR-ND

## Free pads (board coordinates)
  round 0.127 hole 3.1 unplated: 0(3.75,3) 0(3.75,77) 0(61.25,3) 0(61.25,77)
  round 0.25 on Mech16: 1(32.08,38.83) 1(32.08,39.22) 1(32.08,40) 1(32.08,40.39) 1(32.08,40.78) 1(32.08,41.17) 1(32.5,39.61) 1(32.5,40) 1(32.5,40.39) 1(32.92,38.83) 1(32.92,39.22) 1(32.92,39.61) 1(32.92,40.39) 1(32.92,40.78)

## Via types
v1: diameter 0.6, hole 0.3, Top Layer to Bottom Layer, tented both sides, 121 vias
v2: diameter 0.4, hole 0.2, Top Layer to Bottom Layer, tented both sides, 62 vias
v3: diameter 0.25, hole 0.125, Top Layer to Mid-Layer 1, tented top, 8 vias
v4: diameter 0.25, hole 0.125, Top Layer to Mid-Layer 2, tented top, 6 vias

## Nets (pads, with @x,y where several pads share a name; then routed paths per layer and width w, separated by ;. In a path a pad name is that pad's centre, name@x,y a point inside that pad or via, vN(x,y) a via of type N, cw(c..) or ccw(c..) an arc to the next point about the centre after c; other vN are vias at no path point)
BUCK_MODE0: P4.2 U1.G2 | length 41.8
  Top Layer w0.152: P4.2@22.07,6 v2(23.5,6) P4.2@25,6
  Mid-Layer 2 w0.152: v2(27.7,38.4) 28.52,39.22 v4(32.08,39.22)
  Bottom Layer w0.152: v2(23.5,6) 27.6,10.1 27.6,38.233 27.7,38.333 v2(27.7,38.4)
BUCK_MODE1: P5.2 U1.F5 | length 42.3
  Top Layer w0.152: P5.2@28.07,6 v2(29.5,6) P5.2@31,6 ; U1.F5 33.851,39.61 34.188,39.274 35.807,39.274 36.084,39.551 v2(36.151,39.551)
  Bottom Layer w0.152: v2(29.5,6) 30.9,7.4 30.9,33.5 36.1,38.7 36.1,39.338 36.104,39.342 36.104,39.504 v2(36.151,39.551)
BUCK_MODE2: P6.2 U1.G4 | length 41
  Top Layer w0.152: P6.2@34,6 v2(35.5,6) P6.2@36.93,6
  Mid-Layer 1 w0.152: v3(32.929,39.211) 32.92,39.22 32.926,39.226 34.636,39.226 34.862,39 36.438,39 36.442,39.004 36.604,39.004 v2(36.651,39.051)
  Bottom Layer w0.152: v2(35.5,6) 34.621,6.879 34.621,36.371 36.651,38.401 v2@36.651,39.051
ENABLE: P10.2 U1.B2 | length 47.1
  Top Layer w0.152: P10.2@40,6 v2(41.5,6) P10.2@42.93,6
  Mid-Layer 1 w0.152: v3(32.08,41.17) 33,42.09 v2(33,43.7)
  Mid-Layer 4 w0.152: v2(33,43.7) 33,15.2 41.5,6.7 v2(41.5,6)
GND: C1.2 C2.1 C3.1 C4.1 C5.1 C6.2 C7.2 C8.2 C9.2 C10.2 C11.2 C12.1 C13.1 C14.1 C15.1 C16.1 C17.1 C18.2 C19.2 C20.1 C21.1 P1.2 P2.2 P3.2 P4.3 P5.3 P6.3 P7.1 P8.1 P9.1 P10.3 P12.3 P12.4 P13.3 P13.4 P14.3 P14.4 P15.3 P15.4 P19.3 P19.4 P20.3 P20.4 P21.4 TP2.1 TP3.1 TP4.1 TP9.1 TP10.1 U1.A3 U1.B3 U1.E5 U1.F1 U1.F2 U1.F4 U1.G3 U1.H2 U1.H3 U1.J3 U2.B1 | length 21.5
  Top Layer w0.1: U1.G3@32.513,39.22 U1.F4@32.903,39.61 ; U1.F4@32.937,39.61 U1.E5@33.327,40
  Top Layer w0.15: U1.G3 U1.G3@32.513,39.22 ; U1.F4@32.903,39.61 U1.F4 U1.F4@32.937,39.61 ; U1.E5@33.327,40 U1.E5
  Top Layer w0.152: C21.1@10.035,56.05 U2.B1 ; U1.B3 U1.A3 32.507,41.567 32.507,42.785 v2(32.514,42.792)
  Top Layer w0.2: v1(10,56.5) C21.1 C21.1@10.035,56.05 ; C16.1 26.825,39.3 v2(27.7,39.3) ; C10.2 27.9,38.8 27.7,39 v2(27.7,39.3) ; C11.2 27.817,39.9 27.7,39.783 v2(27.7,39.3) ; C4.1 29,42.375 29,41.367 29.117,41.25 29.28,41.25 29.315,41.215 C6.2 ; U1.F2 U1.F1 31.656,39.606 30.421,39.606 C9.2 29.685,39.585 29.4,39.3 v2(27.7,39.3) ; v2(32.5,36.6) U1.J3 U1.H3 U1.G3 ; U1.E5 33.923,40 34.208,39.715 C7.2 34.835,39.75 35.5,39.75 ; C8.2 35.385,38.785 35.987,38.183 35.987,37.688 C2.1 v2(36.7,37.6) ; C3.1 36.784,42.4 36.852,42.468 v2(36.906,42.468)
  other v1: 1.75,1 8,1 18,1 28,1 38,1 47.5,1 57.5,1 63.25,1 10.541,5.695 20.391,5.695 49.941,5.695 59.791,5.695 4.5,6 5.7,8.9 8.7,9.9 63.25,10.5 1.741,10.65 12.991,11.695 32.691,11.695 42.541,11.695 52.391,11.695 62.241,11.695 21.091,11.7 6.891,16.095 6.9,16.1 24.9,16.1 36.441,16.095 46.291,16.095 56.141,16.095 15.7,16.5 3,17 4.5,18 4.5,19 63.3,19.9 4.5,20 22.3,20 42,20 1.741,20.5 3,21.25 12.341,21.395 32.041,21.395 51.241,21.395 45.5,27.5 16.541,29.995 33.8,30 52.5,30 60.8,30 63.25,30 1.741,34.4 59.2,35 31.2,35.1 43.1,35.2 21,35.5 5.6,36.4 11.1,36.5 47,37.5 41.5,38 24.7,39 63.25,40 54.341,40.095 60.8,40.1 1.741,40.2 8,41.5 20.5,43.5 3.5,45.5 10.341,45.495 56.4,45.5 43.7,45.7 32.5,45.8 7.5,47.5 63.25,50 1.741,50.05 11.3,50.1 4,50.5 33.541,50.495 50,50.5 59,50.5 20,50.6 45.4,52.3 13.5,55.8 1.5,58.5 31.041,58.495 46,58.5 19.5,60 38.5,60 63.25,60 22,62 31.85,62 42.809,62.005 2.491,63.995 2.5,64 15.5,64 51.741,63.995 61.591,63.995 6.8,65.9 61.1,67.4 59.2,67.6 63.2,68.5 1.741,69.75 29.041,69.995 48.741,69.995 40,71 52,73 15.6,73.9 62,74.5 13.8,75.2 22.691,75.495 33,77 43,77 1.75,79 8,79 18,79 27.5,79 37.5,79 47.5,79 57,79 63.25,79
  other v2: 26.8,38.7 30.79,47 34.2,47
  other v3: 32.08,38.83
GPIO0: P21.1 U1.C2 | length 43.7
  Top Layer w0.152: P21.1@58.57,53.46 v2(60.035,53.46) P21.1@61.5,53.46
  Mid-Layer 1 w0.152: v2(28.433,41.115) 28.768,40.78 v3(32.08,40.78)
  Bottom Layer w0.152: v2(28.433,41.115) 28.792,40.756 43.395,40.756 56.111,53.472 60.023,53.472 v2(60.035,53.46)
GPIO1: P21.2 U1.D3 | length 37
  Top Layer w0.152: P21.2@58.57,56 v2(60,56) P21.2@61.5,56
  Mid-Layer 2 w0.152: v4(32.5,40.39) 32.893,40.39 33.314,40.811 36.211,40.811 v2(36.7,41.3)
  Bottom Layer w0.152: v2(36.7,41.3) 36.747,41.253 36.879,41.253 36.913,41.219 43.075,41.219 57.856,56 v2(60,56)
GPIO2: P21.3 U1.D2 | length 47.1
  Top Layer w0.152: P21.3@58.57,58.54 58.61,58.5 v2(60,58.5) 61.46,58.5 P21.3@61.5,58.54
  Mid-Layer 1 w0.152: v2(27.731,41.174) 28.515,40.39 v3(32.08,40.39)
  Bottom Layer w0.152: v2(27.731,41.174) 28.513,41.956 43.031,41.956 59.575,58.5 v2(60,58.5)
HOST_SCL: P7.4 P8.4 P9.4 SB1.2 SB4.2 | length 69.8
  Top Layer w0.152: SB1.2 14.788,59.312 15.3,58.8 15.3,56.487 15.1,56.287 SB4.2
  Top Layer w0.2: P8.4 6.95,68.5 9.19,66.26 P7.4@10.9,66.26 ; SB1.2 12.5,63.9 10.9,65.5 P7.4@10.9,66.26 ; v2(15.649,66.216) 15.606,66.26 13.83,66.26 P7.4@10.9,66.26 ; v2(57.8,71.5) P9.4
  Bottom Layer w0.2: v2(15.649,66.216) 49.216,66.216 54.5,71.5 v2(57.8,71.5)
HOST_SDA: P7.3 P8.3 P9.3 SB2.2 SB3.2 | length 76.4
  Top Layer w0.152: P8.3 4.5,69.5 4.25,69.25 4.25,67.5 7,64.75 8,64.75 10.3,62.45 SB2.2 7.712,59.312 6.9,58.5 6.9,56.287 SB3.2
  Top Layer w0.2: P8.3 8.9,69.5 9.6,68.8 10.9,68.8 13.83,68.8 17.4,68.8 18.95,67.25 53.55,67.25 56.8,70.5 P9.3
HOST_VCC: C20.2 P7.2 P8.2 P9.2 R1.2 R2.2 SB7.2 U2.B2 U2.C2 | length 88.5
  Top Layer w0.152: SB7.2 8.8,56.387 8.8,57.4 R2.2 ; U2.C2 12.08,55.55 12.315,55.785 C20.2 C20.2@12.315,55.815 ; U2.B2 12.08,56.05 C20.2@12.315,55.815 ; R1.2 13.9,57.475 12.374,55.949 12.374,55.874 C20.2@12.315,55.815
  Top Layer w0.2: P8.2 8.107,70.5 8.948,71.34 10.9,71.34 12.376,71.34 v2(12.403,71.313) 13.803,71.313 P7.2@13.83,71.34 ; v2(8.1,57.5) R2.2 ; R1.2 13.912,57.512 v2(14.693,57.512) ; v2(57.751,69.497) 59.122,69.497 P9.2
  Mid-Layer 3 w0.2: v2(14.693,57.512) 14.681,57.5 v2(8.1,57.5) 8.1,67.01 v2(12.403,71.313) 20.813,71.313 25,75.5 51.747,75.5 v2(57.751,69.497)
NetP18_3: P18.3 P18.4 | length 8.2
  Top Layer w0.3: P18.4@22.42,70.47 24,70.47 ; P18.4@22.42,73.4 24,73.4 ; P18.3@24.96,70.47 24,70.47 ; P18.3@24.96,73.4 24,73.4 ; 24,70.47 23.824,70.646 23.824,73.224 24,73.4
NetR1_1: R1.1 SB1.1 U2.A2 | length 2.5
  Top Layer w0.152: U2.A2 11.553,56.553 11.578,56.553 12.5,57.475 R1.1 SB1.1
NetR2_1: R2.1 SB2.1 U2.A1 | length 2.5
  Top Layer w0.152: SB2.1 10.289,58.688 10.2,58.598 10.2,57.6 R2.1 10.624,57.176 10.624,56.976 U2.A1
NetR3_1: R3.1 SB6.2 U2.D1 | length 2.7
  Top Layer w0.152: SB6.2 R3.1 10.524,54.424 10.524,54.524 U2.D1
NetR4_1: R4.1 SB5.2 U2.D2 | length 2.7
  Top Layer w0.152: U2.D2 12.076,54.524 12.076,54.424 R4.1 SB5.2
nINT: P11.3 P11.4 R6.1 U1.D4 | length 42.5
  Top Layer w0.2: P11.3 57.278,23.48 57.298,23.5 v1(59,23.5) 61.202,23.5 P11.4 61.238,23.48 61.723,22.995 61.723,21.623 61.1,21 R6.1
  Mid-Layer 1 w0.152: v3(32.92,40.39) 33.436,39.874 34.846,39.874 35.124,40.152 36.348,40.152 48.8,27.7 53.3,27.7 57.5,23.5 v1(59,23.5)
PMIC_SCL: SB4.1 SB5.1 U1.E3 | length 32.4
  Top Layer w0.152: SB5.1@12.399,52.088 SB5.1 12.4,51.667 12.5,51.567 v2(12.5,51.5) 13.8,51.5 15.2,52.9 15.2,55.213 15.1,55.313 SB4.1
  Mid-Layer 2 w0.152: v2(12.5,51.5) 12.5,50.3 17.9,44.9 22.9,44.9 27.3,40.5 30.089,40.5 30.989,39.6 32.177,39.6 32.481,39.905 32.481,39.981 v4(32.5,40)
PMIC_SDA: SB3.1 SB6.1 U1.E2 | length 32.8
  Top Layer w0.152: SB3.1 6.9,55.313 6.9,53.4 8.212,52.088 SB6.1 ; SB6.1@10.209,52.09 10.209,52.066 10.216,52.059 10.216,52.034 11.25,51 v2(14,51)
  Mid-Layer 2 w0.152: v2(14,51) 18.841,46.159 24.041,46.159 29.4,40.8 30.4,40.8 31.2,40 v4(32.08,40)
PMIC_VCC: C1.1 C21.2 P18.2 R3.2 R4.2 R5.2 R6.2 SB7.1 U1.C4 U2.C1 | length 119
  Top Layer w0.152: R3.2 8.8,55.413 ; SB7.1 8.813,55.588 8.886,55.515 9.083,55.515 C21.2 10.032,55.547 11.047,55.547 U2.C1
  Top Layer w0.2: v2(8,54.1) R3.2 ; R4.2 v2(14.5,54.1) ; P18.2@27.5,70.47 P18.2@27.5,73.4 ; v2(38.6,39.5) C1.1 ; R6.2 55,21 53.75,22.25 53.75,27.75 54.5,28.5 v1(57.5,28.5) R5.2
  Mid-Layer 1 w0.2: v3(32.92,40.78) 36.32,40.78 37.6,39.5 v2(38.6,39.5)
  Mid-Layer 2 w0.2: v2(14.5,54.1) 14.5,54.046 14.6,53.946 14.6,53.915 19.315,49.2 36.1,49.2 38.6,46.7 v2(38.6,39.5) 42.1,36 50,36 v1(57.5,28.5)
  Mid-Layer 3 w0.2: v2(8,54.1) v2(14.5,54.1) 14.538,54.062 15.162,54.062 27.5,66.4 v2(27.5,72)
READY: P11.1 P11.2 R5.1 U1.H4 | length 41.1
  Top Layer w0.2: P11.1 57.278,26.02 57.298,26 61.202,26 P11.2 61.238,26.02 61.723,26.505 61.723,27.977 61.2,28.5 R5.1
  Mid-Layer 2 w0.152: v4(32.92,38.83) 33.39,39.3 35.7,39.3 49,26 v1(59,26)
SW0: L1.1 U1.J4 | length 3.6
  Top Layer w0.2: U1.J4 32.92,37.08 33.867,36.133 34.231,36.133 L1.1
SW1: L2.1 U1.A4 | length 3.9
  Top Layer w0.2: U1.A4 32.92,41.96
  Top Layer w0.3: 32.92,41.96 32.92,42.211 34.615,43.906 L2.1
SW2: L3.1 U1.A2 | length 3.9
  Top Layer w0.2: U1.A2 32.08,41.96
  Top Layer w0.3: L3.1 30.385,43.906 32.08,42.211 32.08,41.96
SW3: L4.1 U1.J2 | length 3.4
  Top Layer w0.2: L4.1 30.472,36.3 31.3,36.3 32.08,37.08 U1.J2
VIN: C2.2 C3.2 C4.2 C5.2 C6.1 C7.1 C9.1 C10.1 C11.1 P1.1 P2.1 P3.1 P4.1 P5.1 P6.1 P10.1 P17.1 P17.2 TP1.1 U1.A1 U1.A5 U1.C1 U1.D5 U1.E1 U1.F3 U1.G1 U1.J1 U1.J5 | length 126.4
  Top Layer w0.2: C10.1 v2(29.4,38.8) 29.454,38.8 29.669,39.015 C9.1 30.435,39.05 30.784,39.05 30.964,39.23 31.645,39.23 31.655,39.22 U1.G1 ; C11.1 28.985,39.915 29.02,39.95 29.035,39.95 29.049,39.964 v2@29.8,39.964 ; v2(29.8,40.014) v2@29.8,39.964 ; C6.1 v2(30.4,41.2) 30.438,41.162 30.438,40.897 30.555,40.78 U1.C1 ; 31.463,38.237 31.66,38.435 U1.J1 ; 31.5,41.7 31.515,41.7 31.655,41.56 U1.A1 ; U1.E1 29.89,40 29.854,39.964 v2@29.8,39.964 ; U1.J5 33.505,38.275 33.505,38.2 ; U1.D5 34.156,40.39 34.246,40.3 v2(34.3,40.3) 34.308,40.292 34.792,40.292 C7.1 ; U1.A5 33.345,41.56 33.485,41.7 33.5,41.7 ; P17.1 35.5,70.048 35.5,73.953 P17.2
  Top Layer w0.3: C5.2 v2@30.859,37.6 ; C4.2 v2(31,42.4) 31.019,42.381 31.019,42.181 31.5,41.7 ; v2(30.859,37.591) v2@30.859,37.6 ; v2@30.9,37.6 v2@30.859,37.6 ; 31.463,38.237 30.909,37.684 30.909,37.668 30.859,37.618 v2@30.859,37.6 ; 33.5,41.7 33.981,42.181 33.981,42.381 v2(34,42.4) C3.2 ; 33.505,38.2 v2@34.1,37.605 ; v2(34.1,37.6) C2.2
  Top Layer w0.5: TP1.1 10.5,31 12.7,28.8 12.7,26.174 P1.1 P3.1 16.294,26.076 17.224,26.076 18.8,24.5 18.8,17.5 14.45,13.15 ; P2.1 14.45,13.15 ; P10.1@42.93,8.54 42.87,8.6 19,8.6 14.45,13.15
  Mid-Layer 1 w0.2: v2(29.4,38.8) 30.21,39.61 32.489,39.61 v3(32.489,39.621)
  Mid-Layer 3 w0.2: v2(31,42.4) 30.2,43.2 30.2,54.7 33.23,57.73 33.23,70.23 35,72 v2(35.5,72)
  other v2: 4.5,29.5 4.5,30.25 4.5,31.75 4.5,32.5
VOUT_BUCK0: C8.1 C12.2 L1.2 P12.1 P12.2 P16.1 P16.2 P18.1 TP5.1 U1.C3 U1.G5 U1.H5 | length 82.7
  Top Layer w0.152: P18.1@30.04,70.47 P18.1@30.04,73.4 ; U1.G5 33.78,39.22 34.19,38.81 v2(34.2,38.8)
  Top Layer w0.2: U1.H5 33.53,38.83 ; P16.2 46,70.048 46,73.953 P16.1
  Top Layer w0.3: 33.55,38.81 v2@34.19,38.81 ; v2(34.2,38.8) C8.1
  Mid-Layer 2 w0.1: v4(32.5,40.78) 32.851,41.131 35.611,41.131 35.774,41.294 v2@35.815,41.294
  Mid-Layer 2 w0.3: v2(34.2,38.8) 34.6,38.8 v2(37.6,35.8)
  Mid-Layer 3 w0.2: v2(30.04,71.935) 30.04,72.54 31.5,74 45,74 46,73 v2(46,72) 46,70.2 41.5,65.7 41.5,39.7 v2(37.6,35.8) 37.6,39.196 35.82,40.976 v2(35.82,41.289)
VOUT_BUCK1: C13.2 L2.2 P13.1 P13.2 P17.3 P17.4 TP6.1 U1.B5 | length 33.6
  Top Layer w0.2: U1.B5 33.344,41.174 33.574,41.174 33.6,41.2 ; P17.3 37.5,70.048 v2(37.5,72) 37.5,73.953 P17.4 ; P13.2 39.705,52.278 39.983,52 v2(40,52)
  Top Layer w0.3: 33.6,41.2 33.973,41.2 34.322,41.549 v2(34.322,41.575) ; L2.2 36.385,44.455 36.8,44.04 37.233,44.04 37.273,44 v2(37.3,44)
  Mid-Layer 2 w0.3: v2(34.322,41.575) 36.747,44 v2(37.3,44)
  Mid-Layer 3 w0.2: v2(37.5,72) 37.5,54.5 v2(40,52)
VOUT_BUCK2: C14.2 L3.2 P14.1 P14.2 P16.3 P16.4 TP7.1 U1.B1 | length 41.9
  Top Layer w0.2: v2(25.4,57) 25.953,57 P14.2 ; 31.4,41.2 31.426,41.174 31.656,41.174 U1.B1 ; P16.4 44,70.048 44,73.952 P16.3
  Top Layer w0.3: v2(27.8,44) 27.827,44 27.867,44.04 28.2,44.04 28.615,44.455 L3.2 ; v2(31,41.3) 31.027,41.3 31.127,41.2 31.4,41.2
  Mid-Layer 2 w0.3: v2(27.8,44) 28.307,44 31,41.307 v2(31,41.3)
  Mid-Layer 3 w0.2: v2(25.4,57) 31.4,63 31.4,70.3 34.1,73 43,73 v2(44,72)
VOUT_BUCK3: C15.2 C18.1 L4.2 P15.1 P15.2 TP8.1 U1.H1 | length 6.2
  Top Layer w0.2: 31.47,38.83 U1.H1
  Top Layer w0.3: v2(28.4,36.5) 28.419,36.481 28.941,36.481 L4.2 C15.2 ; v2(30.76,38.6) 30.779,38.619 30.946,38.619 31.157,38.83 31.47,38.83
  Mid-Layer 2 w0.3: v2(28.4,36.5) 28.419,36.519 28.679,36.519 v2(30.76,38.6)
VOUT_VLDO0: C16.2 P20.1 P20.2 TP12.1 U1.D1 | length 26.8
  Top Layer w0.2: C16.2 26.99,40.485 29.986,40.485 30.081,40.39 U1.D1
  Top Layer w0.3: TP12.1 15.7,34.5 17,35.8 P20.1@17,38.73 ; C16.2 23.736,40.675 21.791,38.73 17.223,38.73 P20.1@17,38.73 ; P20.2@12.778,38.73 P20.2 P20.2@12.778,38.73 ; P20.2@12.778,38.73 16.5,38.73 P20.1 P20.1@17,38.73
VOUT_VLDO1: C17.2 C19.1 P19.1 P19.2 TP11.1 U1.C5 | length 26
  Top Layer w0.2: U1.C5 C17.2@37.845,40.78
  Top Layer w0.3: C17.2@37.845,40.78 C17.2 38.89,40.725 C19.1 41.785,40.715 43.77,38.73 P19.2 ; TP11.1 50.476,34.524 49.476,34.524 48.679,35.321 48.679,38.328 P19.2 ; P19.1 49.515,38.73 P19.2
pads on no net: Fid1.0 Fid2.0 Fid3.0 P1.0 P2.0 P8.0 P9.0 U1.B4 U1.E4

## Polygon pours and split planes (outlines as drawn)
VOUT_BUCK0 on Top Layer "VOUT_BUCK0_L01_P004" (solid, remove dead copper, pour order 4): 35.75,36.836 35.75,32.25 37.7,30.3 37.7,21 44.25,21 44.25,31.534 38.948,36.836
VOUT_BUCK1 on Top Layer "VOUT_BUCK1_L01_P017" (solid, remove dead copper, pour order 17): 35.8,43.1 35.8,47.8 37.75,49.75 37.75,59 44.25,59 44.25,47.921 39,43.1
VIN on Top Layer "NONET_L-01_P-001" (solid, pour order 1): 2.25,32.5 3.75,32.5 4,32.75 6.5,32.75 6.5,29.25 4,29.25 3.75,29.5 2.25,29.5
VOUT_BUCK3 on Top Layer "VOUT_BUCK3_L01_P002" (solid, remove dead copper, pour order 2): 29.502,36.9 29.502,32.25 27.25,30.25 27.25,21 20.75,21 20.75,30.958 26.9,36.9
VOUT_BUCK2 on Top Layer "VOUT_BUCK2_L01_P009" (solid, remove dead copper, pour order 9): 29.2,43.1 29.2,47.8 27.25,49.75 27.25,59 20.75,59 20.75,48.45 26.1,43.1
GND on Top Layer "Top_Layer-GND" (solid, remove dead copper, pour order 20): 0.466,80 63.966,80 63.966,0 0.466,0
GND on Mid-Layer 1 "Mid_Layer_1-GND" (solid, pour order 14): 0.75,80 64.25,80 64.25,0 0.75,0
GND on Mid-Layer 3 "Mid_Layer_3-GND" (solid, pour order 18): 0.75,80 64.25,80 64.25,0 0.75,0
VIN on Mid-Layer 3 "VIN_L04_P003" (solid, remove dead copper, pour order 3): 23.1,33.5 27.2,37.6 27.2,43 37.8,43 37.8,35.1 27.9,25.2 6.2,25.2 5.2,26.2 5.2,28.2 3.8,29.6 1,29.6 1,33.5
GND on Mid-Layer 2 "Mid_Layer_2-GND" (solid, pour order 15): 0.75,80 64.25,80 64.25,0 0.75,0
GND on Mid-Layer 4 "Mid_Layer_4-GND" (solid, pour order 16): 0.75,80 64.25,80 64.25,0 0.75,0
GND on Bottom Layer "Bottom_Layer-GND" (solid, pour order 19): 0.75,80 64.25,80 64.25,0 0.75,0

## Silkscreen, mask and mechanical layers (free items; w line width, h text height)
Top Overlay:
  drawing of 38 lines, arcs and shapes, not listed
  text "GND" at 16.001,73.548 h1.5
  text "VCC" at 16.001,71.048 h1.5
  text "SDA" at 16.001,68.548 h1.5
  text "SCL" at 16.001,66.048 h1.5
  text "nPM6001 EK" at 23.075,61.57 h4
  text "GND" at 52.751,60.548 h1.5
  text "GPIO2" at 52.751,58.298 h1.5
  text "GPIO1" at 52.751,55.798 h1.5
  text "GPIO0" at 52.751,53.048 h1.5
  text "READY" at 50.08,25.548 h1.5
  text "N_INT" at 50.528,23.119 h1.5
  text "VIN" at 18.653,8.199 h1
  text "'.PCBNumber'" at 49.25,3.25 h1.5
  text "GND" at 18.183,3.199 h1
  text "'.PCBRevision'" at 49.25,2.25 h1
Top Solder:
  circle w0.7: c32.5,31.75 r0.35
  circle w0.7: c32.5,48.5 r0.35
  circle w0.7: c5.5,31 r0.35
  circle w0.7: c40.5,48.75 r0.35
  circle w0.7: c24.5,48.5 r0.35
  circle w0.7: c25.25,31.75 r0.35
  circle w0.7: c40.25,31.75 r0.35
  circle w0.7: c11.5,19 r0.35
Board Outline:
  the board outline again, w0.1
Top Courtyard:
  pour cut-out: 40.626,21.103 65.845,21.103 65.845,7.675 40.626,7.675
  pour cut-out: 42.864,18.865 63.606,18.865 63.606,9.913 42.864,9.913
  lines w0.125: 42.864,9.913 63.606,9.913 63.606,18.865 42.864,18.865 42.864,9.913

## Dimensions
0.75,1 to 64.25,1 on Dimension
63.25,0 to 63.25,80 on Dimension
